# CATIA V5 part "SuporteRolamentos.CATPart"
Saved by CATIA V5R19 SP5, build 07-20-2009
Part number: SuporteRolamentos.1
Bounding box of the stored display mesh (mm): x -17.5 to 17.5, y 0 to 19, z -25.5 to 25.5
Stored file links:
  Z:\UA\ATLAS\atlascar\ServoPiloto\dir\suportePotenciometro\V2\SuporteRolamentos.CATPart
  Z:\programs_vbox\Dassault Systemes\B19\intel_a\reffiles\standard\MetricThickPitch.txt
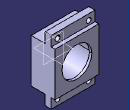
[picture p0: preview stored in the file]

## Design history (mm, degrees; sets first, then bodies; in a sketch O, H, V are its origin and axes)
Body1 (main body)
  Sketch1 on zx-plane, origin (0, 0, 0), H (-1, 0, 0), V (0, 0, 1)
    circle A1 centre (0, 0) radius 13
    line L1 (-17.5, 17.5) -> (17.5, 17.5)
    line L2 (17.5, 17.5) -> (17.5, -17.5)
    line L3 (17.5, -17.5) -> (-17.5, -17.5)
    line L4 (-17.5, -17.5) -> (-17.5, 17.5)
    radius A1 = 13
    distance L1 L3 = 35
    distance L2 L4 = 35
    distance L3 H = 17.5 {= Sketch1.distance(L1 L3) /2}
    distance V L2 = 17.5 {= Sketch1.distance(L2 L4) /2}
    horizontal: L1 H, L3 H
    vertical: L2 V, L4 V
  Pad1: profile Sketch1, direction (0, 1, 0), length 17
  Sketch2 on start face of Pad1, origin (0, 0, 0), H (1, 0, 0), V (0, 0, 1)
    construction circle A1 centre (0, 0) radius 13
    construction line L1 (-17.5, 17.5) -> (17.5, 17.5)
    construction line L2 (17.5, 17.5) -> (17.5, -17.5)
    construction line L3 (17.5, -17.5) -> (-17.5, -17.5)
    construction line L4 (-17.5, -17.5) -> (-17.5, 17.5)
    circle A2 centre (13.5, 13.5) radius 1.25
    point P5 (13.5, 13.5)
    circle A3 centre (-13.5, 13.5) radius 1.25
    circle A4 centre (13.5, -13.5) radius 1.25
    circle A5 centre (-13.5, -13.5) radius 1.25
    radius A1 = 13
    distance L1 L3 = 35
    distance L2 L4 = 35
    distance L3 H = 17.5 {= Sketch2.distance(L1 L3) /2}
    distance V L2 = 17.5 {= Sketch2.distance(L2 L4) /2}
    radius A2 = 1.25
    distance P5 L2 = 4
    distance L1 P5 = 4
    horizontal: L1 H, L3 H
    vertical: L2 V, L4 V
    symmetry: A2 A3 V, A2 A4 H, A3 A5 H
  Pocket1: profile Sketch2, direction (0, 1, 0), length 7
  Sketch3 on end face of Pad1, origin (0, 17, 0), H (-1, 0, 0), V (0, 0, 1)
    circle A1 centre (0, 0) radius 12
    point P1 (0, 0)
    line L1 (-17.5, 17.5) -> (17.5, 17.5)
    line L2 (17.5, 17.5) -> (17.5, -17.5)
    line L3 (17.5, -17.5) -> (-17.5, -17.5)
    line L4 (-17.5, -17.5) -> (-17.5, 17.5)
    reference intersected line E1 (-17.5, 17.5) -> (17.5, 17.5) from face of Pad2
    reference intersected line E2 (17.5, 17.5) -> (17.5, -17.5) from face of Pad2
    reference intersected line E3 (17.5, -17.5) -> (-17.5, -17.5) from face of Pad2
    reference intersected line E4 (-17.5, -17.5) -> (-17.5, 17.5) from face of Pad2
    radius A1 = 12
    coincidence: O P1, L1 E1, E2 L2, E3 L3, L4 E4
    horizontal: L1 H, L3 H
    vertical: L2 V, L4 V
  Pad2: profile Sketch3, direction (0, 1, 0), length 2
  Sketch4 on end face of Pad2, origin (0, 19, 0), H (-1, 0, 0), V (0, 0, 1)
    point P1 (-17.5, 25.5)
    line L1 (-17.5, 25.5) -> (17.5, 25.5)
    line L2 (17.5, 25.5) -> (17.5, 17.5)
    line L3 (17.5, 17.5) -> (-17.5, 17.5)
    line L4 (-17.5, 17.5) -> (-17.5, 25.5)
    point P2 (17.5, 25.5)
    point P3 (17.5, 17.5)
    point P4 (-17.5, 17.5)
    reference projected line E1 (17.5, 17.5) -> (-17.5, 17.5) from edge [face of Pad1 from Sketch1.L1 | end face of Pad1]
    reference projected line E2 (17.5, -17.5) -> (17.5, 17.5) from edge [face of Pad1 from Sketch1.L2 | end face of Pad1]
    reference projected line E3 (-17.5, 17.5) -> (-17.5, -17.5) from edge [face of Pad1 from Sketch1.L4 | end face of Pad1]
    point P5 (-17.5, -25.5)
    point P6 (17.5, -25.5)
    point P7 (17.5, -17.5)
    point P8 (-17.5, -17.5)
    line L5 (-17.5, -25.5) -> (17.5, -25.5)
    line L6 (17.5, -25.5) -> (17.5, -17.5)
    line L7 (17.5, -17.5) -> (-17.5, -17.5)
    line L8 (-17.5, -17.5) -> (-17.5, -25.5)
    length L4 = 8
    horizontal: L1 H, L3 H
    vertical: L2 V, L4 V
    coincidence: E1 L3, E2 L2, L4 E3
    symmetry: P1 P5 H, P2 P6 H, P3 P7 H, P4 P8 H, L1 L5 H, L2 L6 H, L3 L7 H, L4 L8 H
  Pad3: profile Sketch4, direction (0, -1, 0), length 8
  Sketch5 on end face of Pad3, origin (0, 11, 0), H (-1, 0, 0), V (0, 0, 1)
    circle A1 centre (-12.5, 21) radius 2
    point P1 (-12.5, 21)
    circle A2 centre (12.5, 21) radius 2
    point P2 (12.5, 21)
    axis line L1 (-25.619, 21) -> (25.6957, 21)
    reference projected line E1 (-17.5, 17.5) -> (-17.5, -17.5) from edge [face of Pad1 | face of Pad1]
    reference projected line E2 (17.5, -17.5) -> (17.5, 17.5) from edge [face of Pad1 | face of Pad1]
    circle A3 centre (-12.5, -21) radius 2
    circle A4 centre (12.5, -21) radius 2
    radius A2 = 2
    radius A1 = 2 {= Sketch5.radius(A2)}
    distance E1 P1 = 5 {= Sketch5.distance(P2 E2)}
    distance P2 E2 = 5 {= Sketch5.radius(A2) + 3mm}
    distance L1 H = 21
    horizontal: L1 H
    coincidence: P2 L1, P1 L1
    symmetry: A1 A3 H, A2 A4 H
  Pocket2: profile Sketch5, direction (0, -1, 0), through (limit type 6)
  Sketch6 on face of Pad3, origin (0, 19, 0), H (-1, 0, 0), V (0, 0, 1)
    point P1 (-17.5, 25.5)
    line L1 (-17.5, 25.5) -> (17.5, 25.5)
    line L2 (17.5, 25.5) -> (17.5, 17.5)
    line L3 (17.5, 17.5) -> (-17.5, 17.5)
    line L4 (-17.5, 17.5) -> (-17.5, 25.5)
    point P2 (17.5, 25.5)
    point P3 (17.5, 17.5)
    point P4 (-17.5, 17.5)
    reference projected line E1 (-17.5, 17.5) -> (-17.5, -17.5) from edge [face of Pad3 | face of Pad3]
    reference projected line E2 (17.5, -17.5) -> (17.5, 17.5) from edge [face of Pad3 | face of Pad3]
    reference intersected line E3 through (0, 17.5) direction (1, 0) from face of Pad2
    point P5 (17.5, -25.5)
    point P6 (-17.5, -25.5)
    line L5 (-17.5, -25.5) -> (17.5, -25.5)
    point P7 (-17.5, -17.5)
    line L6 (-17.5, -17.5) -> (-17.5, -25.5)
    point P8 (17.5, -17.5)
    line L7 (17.5, -17.5) -> (-17.5, -17.5)
    line L8 (17.5, -25.5) -> (17.5, -17.5)
    distance L1 L3 = 8
    horizontal: L1 H, L3 H
    vertical: L2 V, L4 V
    coincidence: E1 L4, E2 L2, L3 E3
    symmetry: P2 P5 H, P1 P6 H, L1 L5 H, P4 P7 H, L4 L6 H, P3 P8 H, L3 L7 H, L2 L8 H
  Pocket3: profile Sketch6, direction (0, -1, 0), length 3
  Thread1: "M3", diameter 3, depth 7, pitch 0.5, on face of Pocket1 from Sketch2.A4, from start face of Pad1
  Thread2: "M3", diameter 3, depth 7, pitch 0.5, on face of Pocket1 from Sketch2.A5, from start face of Pad1
  Thread3: "M3", diameter 3, depth 7, pitch 0.5, on face of Pocket1 from Sketch2.A2, from start face of Pad1
  Thread4: "M3", diameter 3, depth 7, pitch 0.5, on face of Pocket1 from Sketch2.A3, from start face of Pad1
